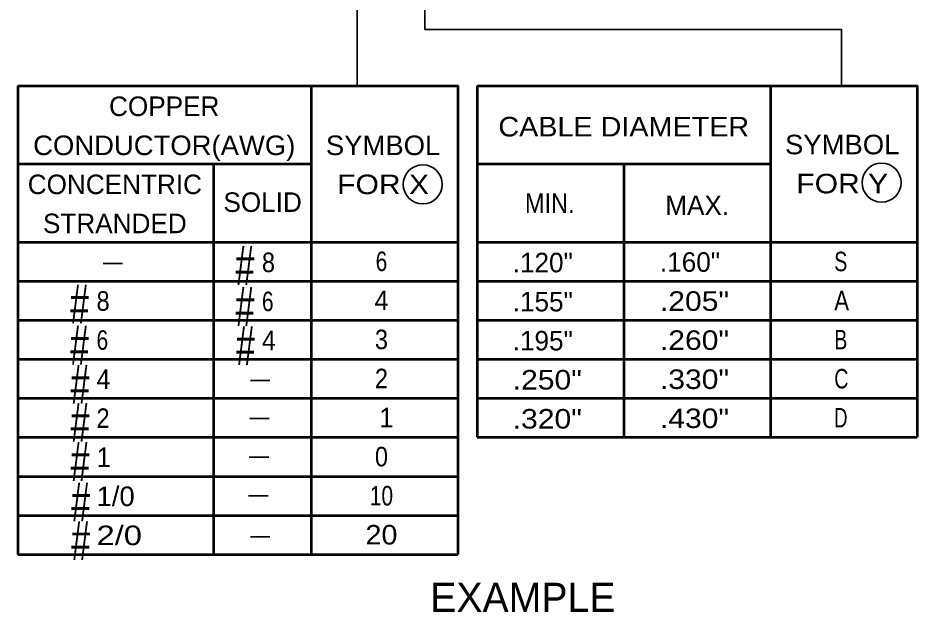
# Model space of a CAD drawing. Extents: x -1 to 679, y 0 to 440.
# Drawn here: x 488.9 to 580.9, y 297.2 to 358 of the extents above; entities that cross this region are included whole.
import ezdxf
from ezdxf.enums import TextEntityAlignment as Align

# ---------------------------------------------------------------- set-up
doc = ezdxf.new("R2010")
doc.units = 0
doc.header["$LTSCALE"] = 0.8
doc.layers.add('1', color=7, linetype='Continuous', lineweight=53)

msp = doc.modelspace()

# ---------------------------------------------------------------- linework, layer by layer
at = {"layer": '1', "lineweight": 35}
for p, q in [((523.6234, 360.2133), (523.6234, 351.0969)), ((530.5331, 360.2133), (530.5331, 356.8522)), ((497.6238, 332.8989), (499.6238, 332.8989)), ((512.6959, 320.9115), (514.6959, 320.9115)), ((512.6329, 317.0215), (514.6329, 317.0215)), ((512.5712, 313.0668), (514.5712, 313.0668)), ((512.5094, 309.1123), (514.5094, 309.1123)), ((512.6947, 304.9105), (514.6947, 304.9105))]:
    msp.add_line(p, q, dxfattribs=at)
at = {"layer": '1'}
for p, q in [((488.9158, 351.0969), (488.9158, 303.0969)), ((518.9158, 351.0969), (518.9158, 303.0969)), ((535.9158, 351.0969), (535.9158, 315.0969)), ((565.9158, 351.0969), (565.9158, 315.0969)), ((488.9158, 343.0969), (518.9158, 343.0969)), ((508.9158, 343.0969), (508.9158, 303.0969)), ((535.9158, 343.0969), (565.9158, 343.0969)), ((550.9158, 343.0969), (550.9158, 315.0969)), ((488.9158, 335.0969), (533.9158, 335.0969)), ((535.9158, 335.0969), (580.9158, 335.0969)), ((488.9158, 331.0969), (533.9158, 331.0969)), ((535.9158, 331.0969), (580.9158, 331.0969)), ((488.9158, 327.0969), (533.9158, 327.0969)), ((535.9158, 327.0969), (580.9158, 327.0969)), ((488.9158, 323.0969), (533.9158, 323.0969)), ((535.9158, 323.0969), (580.9158, 323.0969)), ((488.9158, 319.0969), (533.9158, 319.0969)), ((535.9158, 319.0969), (580.9158, 319.0969)), ((488.9158, 315.0969), (533.9158, 315.0969)), ((535.9158, 315.0969), (580.9158, 315.0969)), ((488.9158, 311.0969), (533.9158, 311.0969)), ((488.9158, 307.0969), (533.9158, 307.0969)), ((488.9158, 303.0969), (533.9158, 303.0969))]:
    msp.add_line(p, q, dxfattribs=at)
at = {"layer": '1', "lineweight": 35}
msp.add_lwpolyline([(530.5331, 356.8522), (573.2007, 356.8522), (573.2007, 351.0969)], dxfattribs=at)
at = {"layer": '1'}
for points in [[(488.9158, 351.0969), (533.9158, 351.0969), (533.9158, 303.0969)], [(535.9158, 351.0969), (580.9158, 351.0969), (580.9158, 315.0969)]]:
    msp.add_lwpolyline(points, dxfattribs=at)
at = {"layer": '1', "lineweight": 35}
for centre in [(577.2867, 341.1757), (530.3392, 341.0007)]:
    msp.add_circle(centre, 2, dxfattribs=at)

# ---------------------------------------------------------------- texts
at = {"layer": '1'}
for s, p in [('COPPER', (503.8825, 347.9982)), ('CONCENTRIC', (498.8275, 340.0015)), ('STRANDED', (498.8275, 336.0015)), ('1', (526.6245, 316.1223))]:
    msp.add_text(s, height=2, dxfattribs=at).set_placement(p, align=Align.CENTER)
for s, height, width, p in [('CABLE DIAMETER', 2, 1.1, (538.0734, 345.909)), ('MIN.', 2, 0.9, (540.7928, 338.0747)), ('#', 4, 0.65, (511.1721, 330.7081)), ('8', 2, 0.9, (513.8801, 332.0139)), ('S', 2, 0.75, (572.4462, 332.1031)), ('#', 4, 0.65, (494.2469, 326.7535)), ('#', 4, 0.65, (511.1721, 326.5063)), ('8', 2, 0.9, (496.9549, 328.0593)), ('6', 2, 0.8, (513.8801, 328.0139)), ('.205"', 2, 1.15, (554.6072, 328.0487)), ('A', 2, 0.85, (572.4462, 328.1031)), ('#', 4, 0.65, (494.2469, 322.5517)), ('6', 2, 0.8, (496.9549, 324.0593)), ('#', 4, 0.65, (511.2338, 322.4899)), ('4', 2, 0.95, (513.8801, 324.0139)), ('.260"', 2, 1.15, (554.6072, 324.0487)), ('B', 2, 0.75, (572.4462, 324.1031)), ('#', 4, 0.65, (494.3087, 318.5353)), ('4', 2, 0.95, (496.9549, 320.0593)), ('.250"', 2, 1.15, (539.5419, 319.9942)), ('.330"', 2, 1.15, (554.6072, 320.0487)), ('C', 2, 0.75, (572.4462, 320.1031)), ('#', 4, 0.65, (494.3087, 314.6426)), ('2', 2, 0.9, (496.9549, 316.0593)), ('.320"', 2, 1.15, (539.5419, 315.9942)), ('.430"', 2, 1.15, (554.6072, 316.0487)), ('D', 2, 0.7, (572.4462, 316.1031)), ('#', 4, 0.65, (494.3087, 310.6262)), ('#', 4, 0.65, (494.3704, 306.4862)), ('1/0', 2, 1.05, (496.9549, 308.0593)), ('#', 4, 0.65, (494.3704, 302.5316)), ('2/0', 2, 1.25, (496.9549, 304.0593))]:
    msp.add_text(s, height=height, dxfattribs=dict(at, width=width)).set_placement(p)
for s, width, p in [('CONDUCTOR(AWG)', 1.05, (503.8825, 343.9982)), ('SYMBOL', 1.05, (526.2775, 343.9998)), ('SYMBOL', 1.05, (573.2621, 344.0799)), ('FOR X', 1.15, (526.2774, 339.9998)), ('FOR Y', 1.15, (573.262, 340.0799)), ('6', 0.8, (526.1106, 332.1223)), ('4', 0.95, (526.1105, 328.1223)), ('3', 0.9, (526.1106, 324.1223)), ('2', 0.9, (526.1106, 320.1223)), ('0', 0.9, (526.1106, 312.1223)), ('10', 0.8, (526.1106, 308.1223)), ('20', 1.1, (526.1105, 304.1223))]:
    msp.add_text(s, height=2, dxfattribs=dict(at, width=width)).set_placement(p, align=Align.CENTER)
for s, height, p in [('SOLID', 2, (509.9367, 338.1783)), ('MAX.', 2, (555.1511, 337.857)), ('.120"', 2, (539.5419, 331.9942)), ('.160"', 2, (554.6072, 332.0487)), ('.155"', 2, (539.5419, 327.9942)), ('.195"', 2, (539.5419, 323.9942)), ('1', 2, (496.9549, 312.0593)), ('EXAMPLE', 3, (531.1039, 297.2068))]:
    msp.add_text(s, height=height, dxfattribs=at).set_placement(p)

doc.saveas('drawing.dxf')
